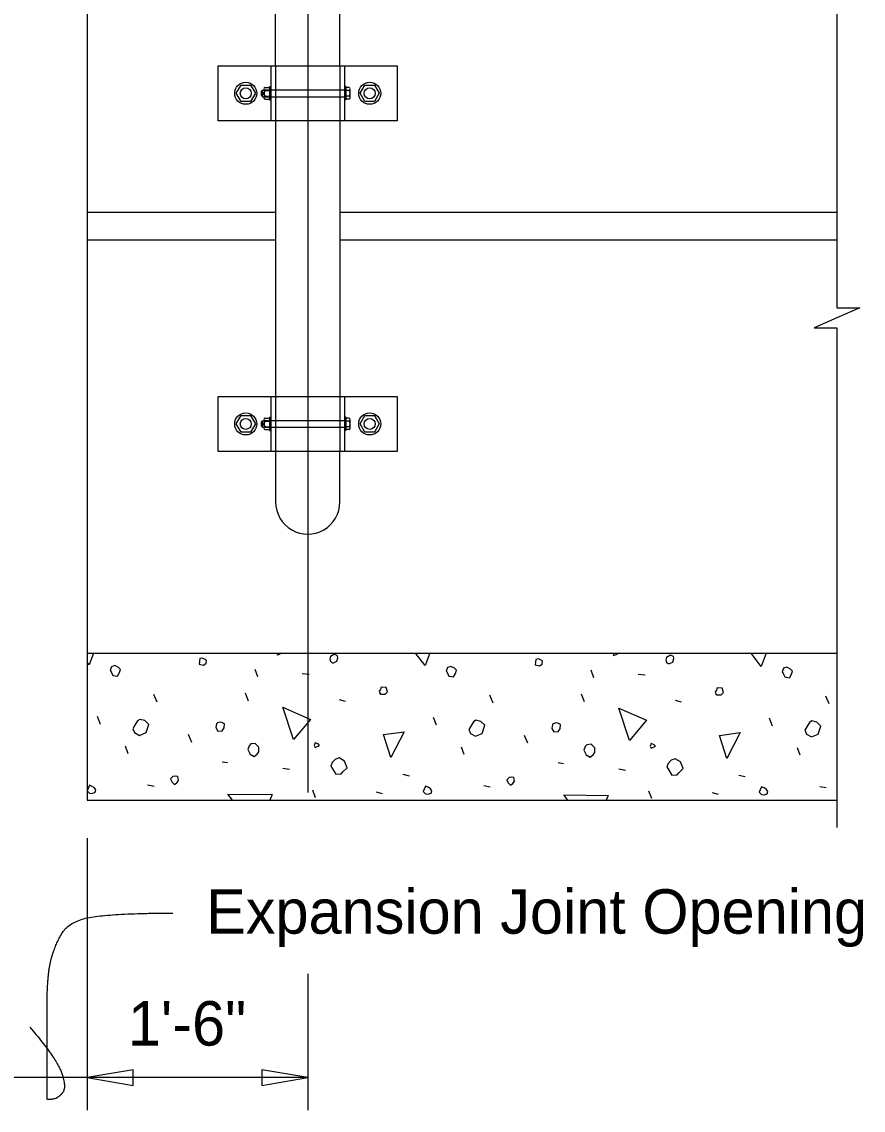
# Model space of a CAD drawing. Extents: x 0.5 to 39.7, y 0.9 to 25.6.
# Drawn here: x 27.279 to 31.095, y 12.062 to 17.001 of the extents above; entities that cross this region are included whole.
import ezdxf

# ---------------------------------------------------------------- set-up
doc = ezdxf.new("R2010")
doc.units = 0
for name, color, linetype in [('CL_Major', 7, 'Continuous'), ('Dimension', 7, 'Continuous'), ('Miscellaneous', 7, 'Continuous'), ('SteelMisc', 7, 'Continuous'), ('SteelMisc_h', 7, 'Continuous'), ('SupstrConc', 7, 'Continuous'), ('TextStructures', 7, 'Continuous')]:
    doc.layers.add(name, color=color, linetype=linetype)

msp = doc.modelspace()

# ---------------------------------------------------------------- linework, layer by layer
at = {"layer": 'CL_Major'}
for p, q in [((28.5763, 25.5043), (28.5763, 13.5039)), ((28.5763, 12.6814), (28.5763, 12.062))]:
    msp.add_line(p, q, dxfattribs=at)
at = {"layer": 'Dimension'}
for p, q in [((27.5763, 13.2961), (27.5763, 12.062)), ((28.5763, 12.21), (26.2429, 12.21))]:
    msp.add_line(p, q, dxfattribs=at)
msp.add_lwpolyline([(30.9761, 17.1361), (30.9761, 15.7022), (31.0795, 15.7022), (30.9761, 15.6572), (30.8728, 15.6122), (30.9761, 15.6122), (30.9761, 13.3448)], dxfattribs=at)
for points in [[(27.5762, 12.2101), (27.7845, 12.1748), (27.7845, 12.2454)], [(28.5762, 12.2101), (28.368, 12.2454), (28.368, 12.1748)]]:
    msp.add_lwpolyline(points, close=True, dxfattribs=at)
msp.add_open_spline([(27.3159, 12.4385), (27.434, 12.3022), (27.4854, 12.1629), (27.437, 12.1114), (27.3939, 12.1114), (27.3939, 12.1114), (27.3939, 12.3628), (27.3939, 12.6656), (27.4249, 12.8019), (27.4975, 12.926), (27.7306, 12.9563), (27.9637, 12.9563)], degree=2, dxfattribs=at)
at = {"layer": 'Miscellaneous'}
for p, q in [((28.3687, 16.6691), (28.3687, 16.6812)), ((28.3744, 16.6691), (28.3744, 16.6812)), ((28.3687, 15.1691), (28.3687, 15.1812)), ((28.3744, 15.1691), (28.3744, 15.1812)), ((29.525, 14.1361), (29.5261, 14.1359)), ((28.3505, 14.0281), (28.3382, 14.0617)), ((28.5503, 14.044), (28.5821, 14.0404)), ((29.8743, 14.0245), (29.862, 14.0581)), ((30.0741, 14.0404), (30.1059, 14.0369)), ((27.8927, 13.9132), (27.8785, 13.9485)), ((28.3081, 13.9185), (28.294, 13.9538)), ((29.4165, 13.9096), (29.4024, 13.945)), ((29.8319, 13.9149), (29.8178, 13.9503)), ((30.9403, 13.9061), (30.9262, 13.9414)), ((28.7182, 13.9255), (28.7465, 13.9185)), ((30.242, 13.922), (30.2703, 13.9149)), ((27.6364, 13.8124), (27.6222, 13.8478)), ((29.1602, 13.8089), (29.146, 13.8442)), ((30.684, 13.8053), (30.6698, 13.8407)), ((28.05, 13.7311), (28.0359, 13.7664)), ((29.5738, 13.7275), (29.5597, 13.7629)), ((27.7619, 13.6798), (27.7495, 13.7134)), ((29.2857, 13.6763), (29.2733, 13.7099)), ((30.8095, 13.6727), (30.7971, 13.7063)), ((28.1879, 13.6427), (28.2126, 13.6392)), ((29.7117, 13.6392), (29.7365, 13.6356)), ((28.4637, 13.6144), (28.4937, 13.6091)), ((29.0081, 13.5861), (29.0364, 13.5791)), ((29.9875, 13.6109), (30.0175, 13.6056)), ((30.532, 13.5826), (30.5602, 13.5755)), ((27.8503, 13.5384), (27.8803, 13.5331)), ((29.3741, 13.5349), (29.4041, 13.5296)), ((28.6122, 13.4801), (28.5998, 13.5136)), ((28.8862, 13.5066), (28.9145, 13.4995)), ((30.136, 13.4765), (30.1236, 13.5101)), ((30.41, 13.503), (30.4383, 13.496)), ((30.8979, 13.5313), (30.9279, 13.526))]:
    msp.add_line(p, q, dxfattribs=at)
for points in [[(27.605, 14.1361), (27.5851, 14.0829)], [(28.4389, 14.1271), (28.4417, 14.1361)], [(28.4591, 14.1361), (28.4389, 14.1271)], [(28.6864, 14.0917), (28.6935, 14.0917), (28.7076, 14.0988), (28.7129, 14.1147), (28.7112, 14.1235), (28.697, 14.1306), (28.6793, 14.12), (28.6758, 14.1094), (28.6793, 14.0988), (28.6864, 14.0917)], [(29.1089, 14.0793), (29.0657, 14.1361)], [(29.1301, 14.1361), (29.1089, 14.0793)], [(29.9627, 14.1235), (29.9666, 14.1361)], [(29.9908, 14.1361), (29.9627, 14.1235)], [(30.2102, 14.0882), (30.2173, 14.0882), (30.2314, 14.0952), (30.2367, 14.1112), (30.235, 14.12), (30.2208, 14.1271), (30.2032, 14.1165), (30.1996, 14.1058), (30.2032, 14.0952), (30.2102, 14.0882)], [(30.6327, 14.0758), (30.5869, 14.1361)], [(30.6553, 14.1361), (30.6327, 14.0758)], [(27.5851, 14.0829), (27.5763, 14.0945)], [(27.6841, 14.051), (27.6929, 14.0351), (27.7141, 14.0316), (27.723, 14.0475), (27.7265, 14.0617), (27.7177, 14.0705), (27.7018, 14.0793), (27.6859, 14.074), (27.6805, 14.0581), (27.6841, 14.051)], [(28.0836, 14.0864), (28.103, 14.0811), (28.1154, 14.0899), (28.1172, 14.1023), (28.1137, 14.1058), (28.0995, 14.1129), (28.0871, 14.1112), (28.0854, 14.0988), (28.0836, 14.0864)], [(29.2079, 14.0475), (29.2167, 14.0316), (29.238, 14.0281), (29.2468, 14.044), (29.2503, 14.0581), (29.2415, 14.067), (29.2256, 14.0758), (29.2097, 14.0705), (29.2044, 14.0546), (29.2079, 14.0475)], [(29.6074, 14.0829), (29.6269, 14.0776), (29.6392, 14.0864), (29.641, 14.0988), (29.6375, 14.1023), (29.6233, 14.1094), (29.611, 14.1076), (29.6092, 14.0952), (29.6074, 14.0829)], [(30.7317, 14.044), (30.7406, 14.0281), (30.7618, 14.0245), (30.7706, 14.0404), (30.7741, 14.0546), (30.7653, 14.0634), (30.7494, 14.0723), (30.7335, 14.067), (30.7282, 14.051), (30.7317, 14.044)], [(28.9056, 13.9503), (28.9268, 13.9503), (28.9374, 13.9609), (28.9321, 13.9803), (28.9091, 13.9821), (28.9056, 13.9715), (28.9003, 13.9627), (28.9056, 13.9503), (28.9021, 13.9538)], [(30.4294, 13.9467), (30.4506, 13.9467), (30.4612, 13.9574), (30.4559, 13.9768), (30.433, 13.9786), (30.4294, 13.968), (30.4241, 13.9591), (30.4294, 13.9467), (30.4259, 13.9503)], [(28.5114, 13.7435), (28.4637, 13.8902), (28.5892, 13.8354), (28.5114, 13.7435)], [(30.0352, 13.7399), (29.9875, 13.8866), (30.113, 13.8318), (30.0352, 13.7399)], [(27.7902, 13.7753), (27.8131, 13.7629), (27.8432, 13.7753), (27.8556, 13.8124), (27.8379, 13.8301), (27.8149, 13.8354), (27.8043, 13.8283), (27.7919, 13.8089), (27.7831, 13.793), (27.7902, 13.7753)], [(29.314, 13.7717), (29.3369, 13.7594), (29.367, 13.7717), (29.3794, 13.8089), (29.3617, 13.8265), (29.3387, 13.8318), (29.3281, 13.8248), (29.3157, 13.8053), (29.3069, 13.7894), (29.314, 13.7717)], [(30.8378, 13.7682), (30.8608, 13.7558), (30.8908, 13.7682), (30.9032, 13.8053), (30.8855, 13.823), (30.8625, 13.8283), (30.8519, 13.8212), (30.8395, 13.8018), (30.8307, 13.7859), (30.8378, 13.7682)], [(28.1596, 13.7983), (28.1685, 13.7823), (28.1879, 13.7841), (28.1967, 13.7965), (28.1985, 13.8159), (28.1861, 13.8212), (28.1773, 13.823), (28.1667, 13.8195), (28.1631, 13.8159), (28.1596, 13.7983)], [(28.9533, 13.6621), (28.9198, 13.7664), (29.0134, 13.7788), (28.9533, 13.6621)], [(29.6834, 13.7947), (29.6923, 13.7788), (29.7117, 13.7806), (29.7206, 13.793), (29.7223, 13.8124), (29.7099, 13.8177), (29.7011, 13.8195), (29.6905, 13.8159), (29.687, 13.8124), (29.6834, 13.7947)], [(28.6104, 13.7081), (28.6298, 13.7169), (28.6228, 13.724), (28.6104, 13.7293), (28.6051, 13.7169), (28.6104, 13.7081)], [(30.4772, 13.6586), (30.4436, 13.7629), (30.5373, 13.7753), (30.4772, 13.6586)], [(28.3046, 13.6993), (28.3152, 13.678), (28.3329, 13.6674), (28.347, 13.678), (28.3541, 13.6887), (28.3541, 13.7099), (28.3382, 13.7258), (28.3187, 13.724), (28.3099, 13.7152), (28.3046, 13.6993)], [(29.8284, 13.6957), (29.839, 13.6745), (29.8567, 13.6639), (29.8708, 13.6745), (29.8779, 13.6851), (29.8779, 13.7063), (29.862, 13.7222), (29.8425, 13.7205), (29.8337, 13.7116), (29.8284, 13.6957)], [(30.1342, 13.7046), (30.1537, 13.7134), (30.1466, 13.7205), (30.1342, 13.7258), (30.1289, 13.7134), (30.1342, 13.7046)], [(28.6811, 13.6232), (28.7041, 13.5861), (28.7271, 13.5879), (28.7359, 13.5967), (28.7554, 13.6162), (28.743, 13.6462), (28.7182, 13.6604), (28.7006, 13.6533), (28.6864, 13.6392), (28.6811, 13.6232)], [(30.2049, 13.6197), (30.2279, 13.5826), (30.2509, 13.5844), (30.2597, 13.5932), (30.2792, 13.6126), (30.2668, 13.6427), (30.242, 13.6568), (30.2244, 13.6498), (30.2102, 13.6356), (30.2049, 13.6197)], [(27.5869, 13.5013), (27.5992, 13.4995), (27.6116, 13.5048), (27.6151, 13.5154), (27.6098, 13.5243), (27.5992, 13.5313), (27.5869, 13.5366), (27.5798, 13.5225), (27.5763, 13.5119), (27.5869, 13.5013)], [(27.9616, 13.5508), (27.9722, 13.5402), (27.9828, 13.5472), (27.9899, 13.5578), (27.9864, 13.5755), (27.9775, 13.5773), (27.9652, 13.5755), (27.9546, 13.5649), (27.9616, 13.5508)], [(29.1107, 13.4977), (29.123, 13.496), (29.1354, 13.5013), (29.139, 13.5119), (29.1337, 13.5207), (29.123, 13.5278), (29.1107, 13.5331), (29.1036, 13.5189), (29.1001, 13.5083), (29.1107, 13.4977)], [(29.4854, 13.5472), (29.496, 13.5366), (29.5067, 13.5437), (29.5137, 13.5543), (29.5102, 13.572), (29.5013, 13.5738), (29.489, 13.572), (29.4784, 13.5614), (29.4854, 13.5472)], [(28.2346, 13.4695), (28.2144, 13.496), (28.4142, 13.4942), (28.4049, 13.4695)], [(29.7557, 13.4695), (29.7382, 13.4924), (29.938, 13.4907), (29.9301, 13.4695)], [(30.6345, 13.4942), (30.6469, 13.4924), (30.6592, 13.4977), (30.6628, 13.5083), (30.6575, 13.5172), (30.6469, 13.5243), (30.6345, 13.5296), (30.6274, 13.5154), (30.6239, 13.5048), (30.6345, 13.4942)]]:
    msp.add_lwpolyline(points, dxfattribs=at)
at = {"layer": 'SteelMisc'}
for p, q in [((28.4305, 16.801), (28.4305, 17.2769)), ((28.7221, 16.801), (28.7221, 17.2769)), ((28.1703, 16.801), (28.9823, 16.801)), ((28.1703, 16.551), (28.1703, 16.801)), ((28.4096, 16.801), (28.4096, 16.551)), ((28.743, 16.801), (28.743, 16.551)), ((28.9823, 16.801), (28.9823, 16.551)), ((28.3781, 16.6939), (28.3781, 16.6582)), ((28.383, 16.702), (28.4031, 16.702)), ((28.4031, 16.7063), (28.4031, 16.6457)), ((28.4031, 16.7063), (28.4096, 16.7063)), ((28.4031, 16.702), (28.4031, 16.65)), ((28.7492, 16.7063), (28.7432, 16.7063)), ((28.7492, 16.7063), (28.7492, 16.6457)), ((28.7639, 16.702), (28.7492, 16.702)), ((28.769, 16.6566), (28.769, 16.6955)), ((28.3659, 16.684), (28.3715, 16.6906)), ((28.3659, 16.6663), (28.3659, 16.684)), ((28.3659, 16.6663), (28.3715, 16.6607)), ((28.3715, 16.6906), (28.3781, 16.6906)), ((28.3715, 16.6607), (28.3715, 16.6906)), ((28.3715, 16.6607), (28.3781, 16.6607)), ((28.3828, 16.689), (28.4031, 16.689)), ((28.3828, 16.6631), (28.4031, 16.6631)), ((28.3831, 16.65), (28.4031, 16.65)), ((28.4031, 16.6457), (28.4096, 16.6457)), ((28.7492, 16.6457), (28.7432, 16.6457)), ((28.7641, 16.689), (28.7492, 16.689)), ((28.7641, 16.663), (28.7492, 16.663)), ((28.7639, 16.65), (28.7492, 16.65)), ((28.9823, 16.551), (28.1703, 16.551)), ((28.4305, 16.551), (28.4305, 15.301)), ((28.7221, 16.551), (28.7221, 15.301)), ((28.1703, 15.301), (28.9823, 15.301)), ((28.1703, 15.051), (28.1703, 15.301)), ((28.4096, 15.301), (28.4096, 15.051)), ((28.743, 15.301), (28.743, 15.051)), ((28.9823, 15.301), (28.9823, 15.051)), ((28.3659, 15.184), (28.3715, 15.1906)), ((28.3659, 15.1663), (28.3659, 15.184)), ((28.3659, 15.1663), (28.3715, 15.1607)), ((28.3715, 15.1906), (28.3781, 15.1906)), ((28.3715, 15.1607), (28.3715, 15.1906)), ((28.3781, 15.1939), (28.3781, 15.1582)), ((28.3828, 15.189), (28.4031, 15.189)), ((28.3828, 15.1631), (28.4031, 15.1631)), ((28.383, 15.202), (28.4031, 15.202)), ((28.4031, 15.2063), (28.4031, 15.1457)), ((28.4031, 15.2063), (28.4096, 15.2063)), ((28.4031, 15.202), (28.4031, 15.15)), ((28.7492, 15.2063), (28.7432, 15.2063)), ((28.7492, 15.2063), (28.7492, 15.1457)), ((28.7639, 15.202), (28.7492, 15.202)), ((28.7641, 15.189), (28.7492, 15.189)), ((28.7641, 15.163), (28.7492, 15.163)), ((28.769, 15.1566), (28.769, 15.1955)), ((28.3715, 15.1607), (28.3781, 15.1607)), ((28.3831, 15.15), (28.4031, 15.15)), ((28.4031, 15.1457), (28.4096, 15.1457)), ((28.7492, 15.1457), (28.7432, 15.1457)), ((28.7639, 15.15), (28.7492, 15.15)), ((28.9823, 15.051), (28.1703, 15.051)), ((28.4303, 15.051), (28.4303, 14.8218)), ((28.722, 14.8218), (28.722, 15.051))]:
    msp.add_line(p, q, dxfattribs=at)
for points in [[(28.2736, 16.7135), (28.317, 16.7135), (28.3386, 16.676), (28.317, 16.6385), (28.2736, 16.6385), (28.252, 16.676)], [(28.8356, 16.7135), (28.8789, 16.7135), (28.9006, 16.676), (28.8789, 16.6385), (28.8356, 16.6385), (28.8139, 16.676)], [(28.2736, 15.2135), (28.317, 15.2135), (28.3386, 15.176), (28.317, 15.1385), (28.2736, 15.1385), (28.252, 15.176)], [(28.8356, 15.2135), (28.8789, 15.2135), (28.9006, 15.176), (28.8789, 15.1385), (28.8356, 15.1385), (28.8139, 15.176)]]:
    msp.add_lwpolyline(points, close=True, dxfattribs=at)
for centre, radius in [((28.2953, 16.676), 0.05), ((28.2953, 16.676), 0.025), ((28.8573, 16.676), 0.05), ((28.8573, 16.676), 0.025), ((28.2953, 15.176), 0.05), ((28.8573, 15.176), 0.05), ((28.2953, 15.176), 0.025), ((28.8573, 15.176), 0.025)]:
    msp.add_circle(centre, radius, dxfattribs=at)
for centre, radius, start, end in [((28.3846, 16.6955), 0.00674, 104.4891, 254.1889), ((28.7622, 16.6955), 0.00673, 285.7823, 75.5404), ((28.3975, 16.676), 0.0196, 138.628, 221.372), ((28.3846, 16.6565), 0.00673, 105.7823, 255.5404), ((28.7622, 16.6565), 0.00674, 284.4891, 74.1889), ((28.7493, 16.676), 0.0196, 318.628, 41.372), ((28.3846, 15.1955), 0.00674, 104.4891, 254.1889), ((28.3975, 15.176), 0.0196, 138.628, 221.372), ((28.3846, 15.1565), 0.00673, 105.7823, 255.5404), ((28.7622, 15.1955), 0.00673, 285.7823, 75.5404), ((28.7622, 15.1565), 0.00674, 284.4891, 74.1889), ((28.7493, 15.176), 0.0196, 318.628, 41.372)]:
    msp.add_arc(centre, radius, start, end, dxfattribs=at)
msp.add_ellipse((28.5763, 14.8218), major_axis=(0, 0.1458), ratio=0.999499, start_param=1.570796, end_param=4.712389, dxfattribs=at)
at = {"layer": 'SteelMisc_h'}
for p, q in [((28.4305, 16.801), (28.4305, 16.551)), ((28.7221, 16.801), (28.7221, 16.551)), ((28.743, 16.6906), (28.3781, 16.6906)), ((28.3781, 16.6607), (28.743, 16.6607)), ((28.4305, 15.301), (28.4305, 15.051)), ((28.7221, 15.301), (28.7221, 15.051)), ((28.743, 15.1906), (28.3781, 15.1906)), ((28.3781, 15.1607), (28.743, 15.1607))]:
    msp.add_line(p, q, dxfattribs=at)
at = {"layer": 'SupstrConc'}
for p, q in [((27.5763, 17.1361), (27.5763, 13.4695)), ((27.5763, 16.1361), (28.4305, 16.1361)), ((28.7221, 16.1361), (30.976, 16.1361)), ((27.5763, 16.0111), (28.4305, 16.0111)), ((28.7221, 16.0111), (30.976, 16.0111)), ((27.5763, 14.1361), (30.9761, 14.1361)), ((27.5763, 13.4695), (30.9761, 13.4695))]:
    msp.add_line(p, q, dxfattribs=at)

# ---------------------------------------------------------------- texts
at = {"layer": 'TextStructures'}
for s, p in [('Expansion Joint Opening', (28.1153, 12.863)), ('1\'-6"', (27.7605, 12.3553))]:
    msp.add_text(s, height=0.2016, dxfattribs=at).set_placement(p)

doc.saveas('drawing.dxf')
